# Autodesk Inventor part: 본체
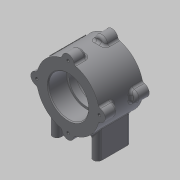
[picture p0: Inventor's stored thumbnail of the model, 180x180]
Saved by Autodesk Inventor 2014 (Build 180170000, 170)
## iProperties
Created: 2015-03
Part Number: 본체
Material: Generic
Document SubType Name: Modeling
Designer: MYHOME
Density: 1 g/cm^3
Appearance: Default
Author: MYHOME
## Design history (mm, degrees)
sketch "스케치2"
  geometry: C1 r 37 at (0, 0); 1 further point
  constraints: 1 centre point, 1 coincident
  dimensions: "d0" = 74 diameter of C1
extrude "돌출1" new body sketch "스케치2" stored distance "d1" = 52; taper "d2" = 0 deg
node "작업 평면1"
sketch "스케치3"
  geometry: L1 (-24, 15)-(-24, -15); L2 (-19, 15)-(-19, -15); L3 (-29, -15)-(-29, 15); L4 (24, 15)-(24, -15); L5 (29, 15)-(29, -15); L6 (19, -15)-(19, 15); A1 r 5 centre (-24, 15) between (-19, 15) and (-29, 15); A2 r 5 centre (-24, -15) between (-29, -15) and (-19, -15); A3 r 5 centre (24, 15) between (29, 15) and (19, 15); A4 r 5 centre (24, -15) between (19, -15) and (29, -15); 3 further points
  constraints: 16 end point, 8 point on circle, 8 tangent, 4 centre point, 3 parallel, 2 horizontal alignment, 2 midpoint, 1 vertical
  dimensions: "d4" = 10 distance between parallel lines of L3 L2; "d5" = 10 distance between parallel lines of L5 L6; "d6" = 48 distance of point (24, 0) point (-24, 0); "d7" = 40 dimension on A4 A3; "d8" = 40 dimension on A2 A1; "d9" = 24 distance of point (0, 0) point (-24, 0)
extrude "돌출2" join sketch "스케치3" stored distance "d10" = 52; taper "d11" = 0 deg
sketch "스케치4"
  geometry: C1 r 7 at (0, 37); C2 r 7 at (-37, 0); C3 r 7 at (0, -37); C4 r 7 at (37, 0); A1 r 37 centre (0, 0) between (0, 37) and (37, 0) reference
  constraints: 4 centre point, 4 point on circle, 2 horizontal alignment, 2 vertical alignment
  dimensions: "d12" = 14 diameter of C1; "d13" = 14 diameter of C4; "d14" = 14 diameter of C3; "d15" = 14 diameter of C2
extrude "돌출3" join sketch "스케치4" distance "d16" = 15; taper "d17" = 0 deg
sketch "스케치5"
  geometry: A1 r 7 centre (0, 37) between (6.969, 36.338) and (-6.969, 36.338) reference; A2 r 7 centre (-37, 0) between (-36.338, 6.969) and (-36.338, -6.969) reference; A3 r 7 centre (0, -37) between (-6.969, -36.338) and (6.969, -36.338) reference; A4 r 7 centre (37, 0) between (36.338, -6.969) and (36.338, 6.969) reference; 4 further points
  constraints: 4 coincident
hole "구멍1" sketch "스케치5" at (37, 0), (0, 37), (-37, 0), (0, -37) diameter "d18" = 3.242; stored, may be unused: countersink angle "d22" = 90 deg, drill point angle "d24" = 118 deg; dims "d19" = 8, "d20" = 4, "d21" = 2, "d23" = 11
hole "구멍2" diameter "d27" = 42; stored, may be unused: countersink angle "d31" = 90 deg, drill point angle "d33" = 0 deg; dims "d25" = 10, "d26" = 10, "d28" = 8, "d29" = 47, "d30" = 22, "d32" = 30
sketch "스케치6"
  geometry: C1 r 23.5 at (0, 0); A1 r 37 centre (0, 0) between (6.969, -36.338) and (36.338, -6.969) reference
  constraints: 1 centre point, 1 coincident
  dimensions: "d34" = 47 diameter of C1
extrude "돌출4" cut sketch "스케치6" distance "d35" = 22; taper "d36" = 0 deg
sketch "스케치7"
  geometry: L1 (19, 15)-(19, -15) reference; L2 (29, -15)-(29, 15) reference; A1 r 5 centre (-24, -15) between (-29, -15) and (-19, -15) reference; A2 r 5 centre (-24, 15) between (-19, 15) and (-29, 15) reference; A3 r 5 centre (24, -15) between (19, -15) and (29, -15) reference; A4 r 5 centre (24, 15) between (29, 15) and (19, 15) reference; 5 further points
  constraints: 4 coincident
hole "구멍3" sketch "스케치7" at (-24, 15), (-24, -15), (24, 15), (24, -15) diameter "d37" = 4.134; stored, may be unused: countersink angle "d41" = 90 deg, drill point angle "d43" = 118 deg; dims "d38" = 6, "d39" = 47, "d40" = 22, "d42" = 8
fillet "모깎기1" dims "d44" = 3
fillet "모깎기2" dims "d45" = 3
fillet "모깎기3" dims "d46" = 0.3
chamfer "모따기1" distance "d47" = 1; stored, may be unused: second distance "d48" = 2, angle "d49" = 45 deg
sketch "스케치8"
  geometry: L1 (21, 0)-(0, 0); L2 (0, 0)-(26.163, 26.163); A1 r 37 centre (0, 0) between (35.862, 9.104) and (9.104, 35.862) reference; 2 further points
  constraints: 4 end point, 1 horizontal, 1 horizontal alignment, 1 point on circle, 1 other
  dimensions: "d50" = 45 deg angle of L2 L1
node "작업 평면2"
sketch "스케치10"
  geometry: 2 further points
  constraints: 1 coincident, 1 other
feature "엠보싱2" sketch "스케치10" dims "d53" = 0.5, "d54" = 0
fillet "모깎기4" dims "d55" = 3
node "솔리드1"
mirror "대칭1"
node "투영된 루프1"
other parameters: "d3" = -56
